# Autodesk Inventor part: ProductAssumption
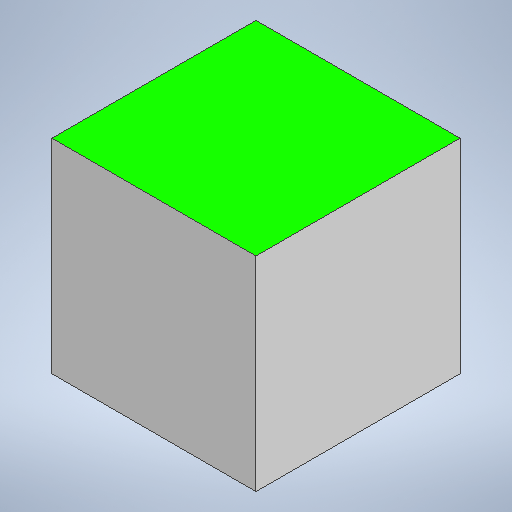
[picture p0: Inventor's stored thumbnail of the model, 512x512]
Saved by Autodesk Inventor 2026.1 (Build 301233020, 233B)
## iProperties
Created: 2026-11
Part Number: ProductAssumption
Material: Generic
Document SubType Name: Modeling
Designer: hp
Density: 1 g/cm^3
Appearance: Default
Author: hp
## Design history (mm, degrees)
sketch "Sketch1"
  geometry: L1 (-20, 20)-(20, 20); L2 (20, 20)-(20, -20); L3 (20, -20)-(-20, -20); L4 (-20, -20)-(-20, 20); L5 (-20, 20)-(20, -20); L6 (20, 20)-(-20, -20); 1 further point
  constraints: 12 end point, 2 midpoint, 2 parallel, 1 horizontal, 1 perpendicular
  dimensions: "d0" = 40 distance of L2.end L3.end; "d1" = 40 distance of L1.end L2.end
extrude "Extrusion1" new body sketch "Sketch1" distance "d2" = 40; taper "d3" = 0 deg
body "Solid1"
